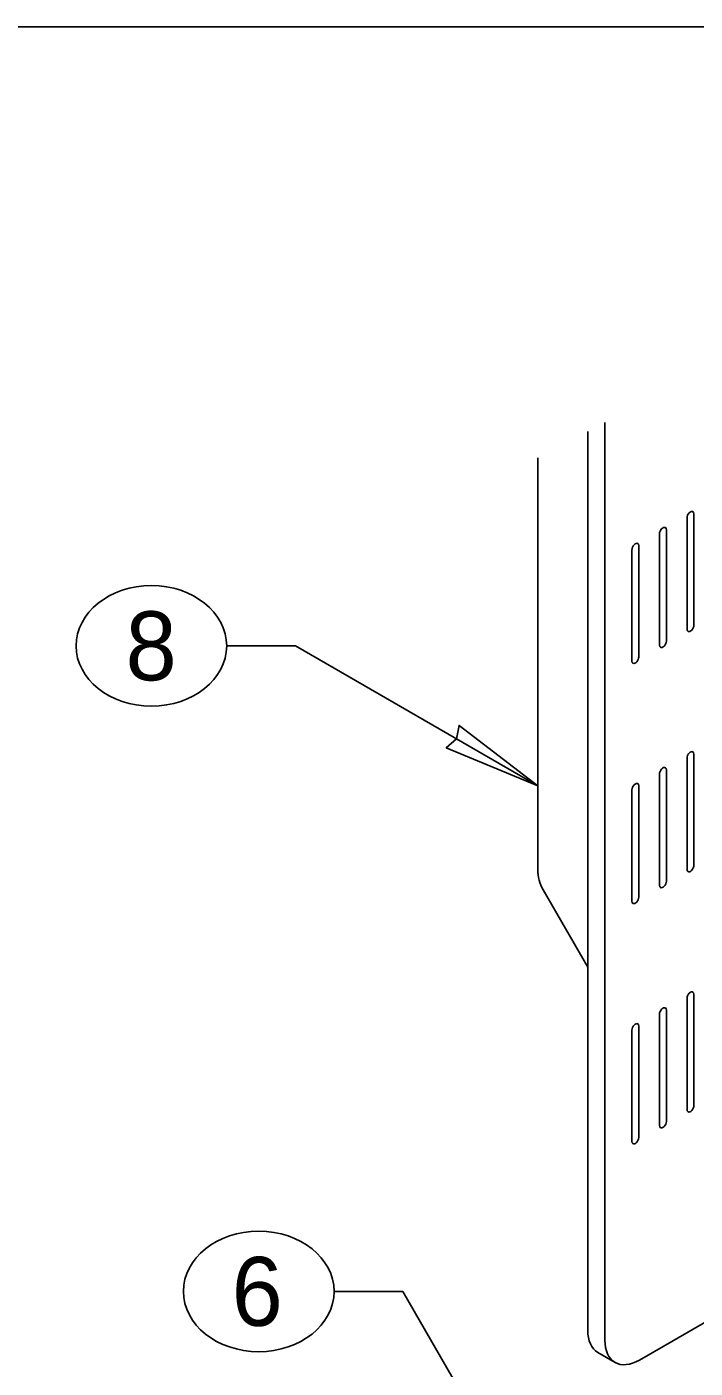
# Model space of a CAD drawing. Extents: x 99862 to 104211, y 98939 to 102076.
# Drawn here: x 101538.3 to 101693.6, y 101763.9 to 102075.5 of the extents above; entities that cross this region are included whole.
import ezdxf

# ---------------------------------------------------------------- set-up
doc = ezdxf.new("R2010")
doc.units = 0
for name, color, linetype in [('Level 1', 7, 'Continuous'), ('Level 15', 7, 'Continuous'), ('Level 20', 7, 'Continuous'), ('Level 9', 7, 'Continuous')]:
    doc.layers.add(name, color=color, linetype=linetype)

msp = doc.modelspace()

# ---------------------------------------------------------------- linework, layer by layer
at = {"layer": 'Level 1'}
msp.add_lwpolyline([(99862, 99999.5), (103151, 99999.5), (103151, 102075.5), (99862, 102075.5)], close=True, dxfattribs=at)
at = {"layer": 'Level 15'}
for p, q in [((101584.71, 101931.7), (101600.71, 101931.7)), ((101657, 101899.2), (101600.71, 101931.7)), ((101609.66, 101781.74), (101625.66, 101781.74)), ((101658.16, 101725.45), (101625.66, 101781.74))]:
    msp.add_line(p, q, dxfattribs=at)
msp.add_lwpolyline([(101657, 101899.2), (101635.74, 101908.03), (101638.14, 101910.08), (101638.72, 101913.2)], close=True, dxfattribs=at)
at = {"layer": 'Level 20'}
for centre in [(101567.21, 101931.7), (101592.16, 101781.74)]:
    msp.add_ellipse(centre, major_axis=(-17.5, 0), ratio=0.8, dxfattribs=at)
at = {"layer": 'Level 9'}
for p, q in [((101668.61, 101981.46), (101668.61, 101772.73)), ((101672.61, 101983.56), (101672.61, 101770.42)), ((101657, 101879.7), (101657, 101975.34)), ((101691.68, 101935.57), (101691.68, 101961.43)), ((101693.28, 101962.36), (101693.28, 101936.5)), ((101685.28, 101931.88), (101685.28, 101957.74)), ((101686.88, 101958.66), (101686.88, 101932.8)), ((101678.88, 101928.18), (101678.88, 101954.04)), ((101680.48, 101954.97), (101680.48, 101929.11)), ((101691.68, 101879.78), (101691.68, 101905.64)), ((101693.28, 101906.56), (101693.28, 101880.7)), ((101685.28, 101876.08), (101685.28, 101901.94)), ((101686.88, 101902.87), (101686.88, 101877.01)), ((101678.88, 101872.39), (101678.88, 101898.25)), ((101680.48, 101899.17), (101680.48, 101873.31)), ((101668.61, 101857.08), (101658.26, 101875.01)), ((101693.28, 101850.77), (101693.28, 101824.91)), ((101691.68, 101823.98), (101691.68, 101849.84)), ((101685.28, 101820.29), (101685.28, 101846.15)), ((101686.88, 101847.07), (101686.88, 101821.21)), ((101678.88, 101816.59), (101678.88, 101842.45)), ((101680.48, 101843.38), (101680.48, 101817.52)), ((101680.61, 101765.8), (101785.87, 101826.58)), ((101670.95, 101767.55), (101674.95, 101765.24))]:
    msp.add_line(p, q, dxfattribs=at)
msp.add_arc((101666.38, 101879.7), 9.37, 180, 210, dxfattribs=at)
for centre, major_axis, start_param, end_param in [((101692.48, 101961.9), (-0.566, -0.98), 3.141593, 5.497787), ((101692.48, 101961.9), (-0.566, -0.98), 2.356194, 3.141593), ((101686.08, 101958.2), (-0.566, -0.98), 3.141593, 5.497787), ((101686.08, 101958.2), (-0.566, -0.98), 2.356194, 3.141593), ((101679.68, 101954.51), (-0.566, -0.98), 3.141593, 5.497787), ((101679.68, 101954.51), (-0.566, -0.98), 2.356194, 3.141593), ((101692.48, 101936.03), (-0.566, -0.98), 5.497787, 6.283185), ((101692.48, 101936.03), (-0.566, -0.98), 0, 2.356194), ((101686.08, 101932.34), (-0.566, -0.98), 5.497787, 6.283185), ((101686.08, 101932.34), (-0.566, -0.98), 0, 2.356194), ((101679.68, 101928.64), (-0.566, -0.98), 0, 2.356194), ((101679.68, 101928.64), (-0.566, -0.98), 5.497787, 6.283185), ((101692.48, 101906.1), (-0.566, -0.98), 3.141593, 5.497787), ((101692.48, 101906.1), (-0.566, -0.98), 2.356194, 3.141593), ((101686.08, 101902.41), (-0.566, -0.98), 3.141593, 5.497787), ((101686.08, 101902.41), (-0.566, -0.98), 2.356194, 3.141593), ((101679.68, 101898.71), (-0.566, -0.98), 3.141593, 5.497787), ((101679.68, 101898.71), (-0.566, -0.98), 2.356194, 3.141593), ((101692.48, 101880.24), (-0.566, -0.98), 5.497787, 6.283185), ((101692.48, 101880.24), (-0.566, -0.98), 0, 2.356194), ((101686.08, 101876.54), (-0.566, -0.98), 5.497787, 6.283185), ((101686.08, 101876.54), (-0.566, -0.98), 0, 2.356194), ((101679.68, 101872.85), (-0.566, -0.98), 5.497787, 6.283185), ((101679.68, 101872.85), (-0.566, -0.98), 0, 2.356194), ((101692.48, 101850.31), (-0.566, -0.98), 3.141593, 5.497787), ((101692.48, 101850.31), (-0.566, -0.98), 2.356194, 3.141593), ((101686.08, 101846.61), (-0.566, -0.98), 3.141593, 5.497787), ((101686.08, 101846.61), (-0.566, -0.98), 2.356194, 3.141593), ((101679.68, 101842.92), (-0.566, -0.98), 3.141593, 5.497787), ((101679.68, 101842.92), (-0.566, -0.98), 2.356194, 3.141593), ((101692.48, 101824.44), (-0.566, -0.98), 5.497787, 6.283185), ((101692.48, 101824.44), (-0.566, -0.98), 0, 2.356194), ((101686.08, 101820.75), (-0.566, -0.98), 5.497787, 6.283185), ((101686.08, 101820.75), (-0.566, -0.98), 0, 2.356194), ((101679.68, 101817.05), (-0.566, -0.98), 5.497787, 6.283185), ((101679.68, 101817.05), (-0.566, -0.98), 0, 2.356194), ((101676.61, 101777.35), (-5.66, -9.8), 5.497787, 6.283185), ((101680.61, 101775.04), (5.66, 9.8), 2.356194, 3.141593), ((101680.61, 101775.04), (5.66, 9.8), 3.141593, 3.926991)]:
    msp.add_ellipse(centre, major_axis=major_axis, ratio=0.57735, start_param=start_param, end_param=end_param, dxfattribs=at)

# ---------------------------------------------------------------- texts
at = {"layer": 'Level 20'}
for s, p in [('8', (101561.2, 101923.7)), ('6', (101585.85, 101773.74))]:
    msp.add_text(s, height=16, dxfattribs=at).set_placement(p)

doc.saveas('drawing.dxf')
